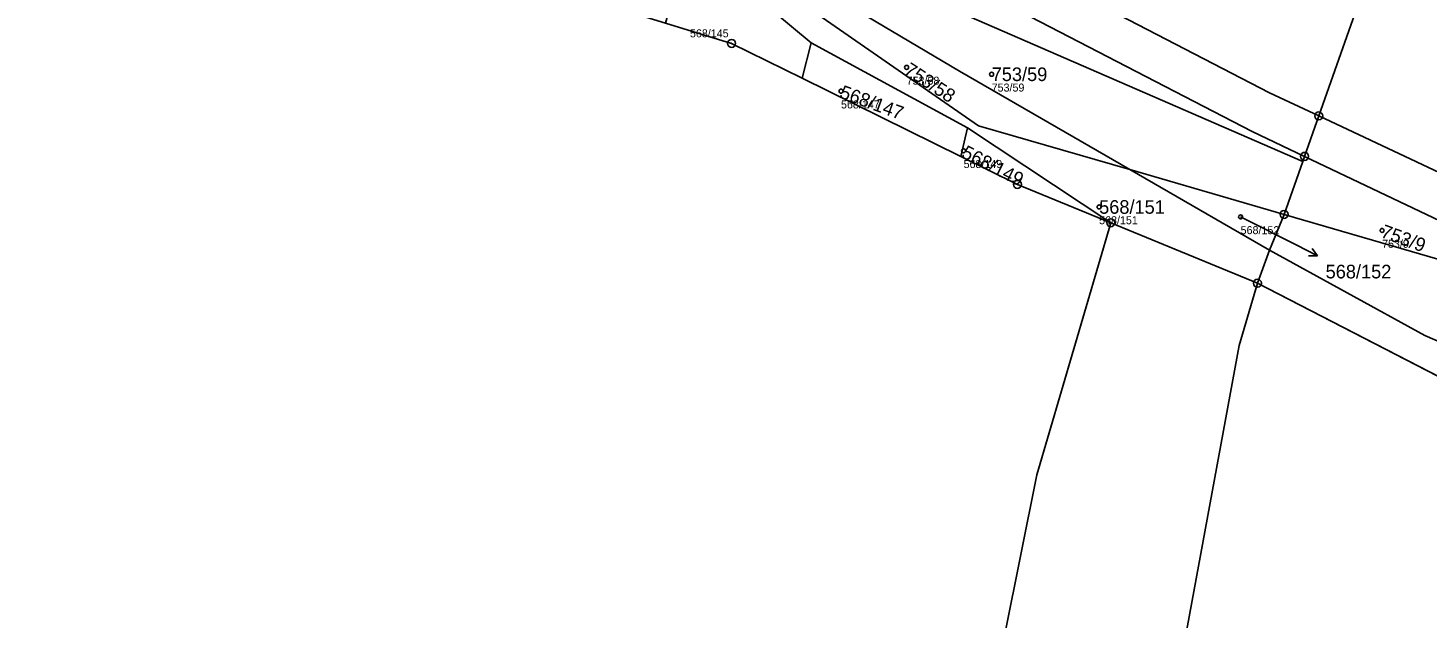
# Model space of a CAD drawing. Extents: x -732749 to -730903, y -1025757 to -1023435.
# Drawn here: x -731284.8 to -731109.9, y -1024442.6 to -1024368.8 of the extents above; entities that cross this region are included whole.
import ezdxf

# ---------------------------------------------------------------- set-up
doc = ezdxf.new("R2010")
doc.units = 0
for name, color, linetype in [('Definiční body', 7, 'Continuous'), ('Hranice parcel', 7, 'Continuous'), ('Parcelní čísla', 7, 'Continuous'), ('Polygon parcely', 7, 'Continuous'), ('Pop  PČ popisy', 7, 'Continuous'), ('Značky bodu BP', 7, 'Continuous')]:
    doc.layers.add(name, color=color, linetype=linetype)

msp = doc.modelspace()

# ---------------------------------------------------------------- linework, layer by layer
at = {"layer": 'Definiční body'}
for centre in [(-731174.97, -1024373.73), (-731164.34, -1024374.59), (-731183.17, -1024376.7), (-731167.85, -1024384.15), (-731150.91, -1024391.18), (-731133.22, -1024392.42), (-731115.54, -1024394.12)]:
    msp.add_circle(centre, 0.25, dxfattribs=at)
at = {"layer": 'Hranice parcel'}
for p, q in [((-731110.5, -1024343.03), (-731123.45, -1024379.8)), ((-731188.01, -1024375.09), (-731186.88, -1024370.67)), ((-731167.34, -1024381.29), (-731186.88, -1024370.67)), ((-731168.19, -1024384.86), (-731188.01, -1024375.09)), ((-731123.45, -1024379.8), (-731125.23, -1024384.85)), ((-731168.19, -1024384.86), (-731167.34, -1024381.29)), ((-731149.46, -1024393.15), (-731167.34, -1024381.29)), ((-731125.45, -1024385.48), (-731127.79, -1024392.11)), ((-731125.23, -1024384.85), (-731125.45, -1024385.48)), ((-731129.61, -1024396.6), (-731147.08, -1024386.51)), ((-731127.79, -1024392.11), (-731147.08, -1024386.51)), ((-731129.61, -1024396.6), (-731127.79, -1024392.11)), ((-731131.12, -1024400.71), (-731149.46, -1024393.15)), ((-731131.12, -1024400.71), (-731129.61, -1024396.6)), ((-731093.47, -1024420.12), (-731131.12, -1024400.71))]:
    msp.add_line(p, q, dxfattribs=at)
for points in [[(-731123.45, -1024379.8), (-731129.62, -1024376.9), (-731164.85, -1024358.61), (-731179.99, -1024347.06), (-731182.99, -1024344.27)], [(-731125.23, -1024384.85), (-731131.78, -1024381.73), (-731167.95, -1024362.97), (-731184.06, -1024350.96), (-731185.99, -1024349.07)], [(-731188.43, -1024352.97), (-731173.87, -1024364.4), (-731125.45, -1024385.48)], [(-731147.08, -1024386.51), (-731168.38, -1024374.2), (-731185.11, -1024364.22), (-731192.24, -1024359.06)], [(-731147.08, -1024386.51), (-731165.97, -1024381.02), (-731193.95, -1024361.63)], [(-731186.88, -1024370.67), (-731194.77, -1024364.06), (-731195.28, -1024363.64)], [(-731188.01, -1024375.09), (-731196.85, -1024370.73), (-731205.11, -1024368.19)], [(-731076.41, -1024398.3), (-731084.09, -1024396.18), (-731104.77, -1024388.59), (-731123.45, -1024379.8)], [(-731149.46, -1024393.15), (-731161.12, -1024388.35), (-731168.19, -1024384.86)], [(-731125.23, -1024384.85), (-731107.45, -1024393.31), (-731077.68, -1024402.89)], [(-731127.79, -1024392.11), (-731086.48, -1024404.11), (-731078.65, -1024406.4)], [(-731174.98, -1024506.17), (-731174.6, -1024503.96), (-731158.69, -1024424.65), (-731149.46, -1024393.15)], [(-731129.61, -1024396.6), (-731110.2, -1024407.27), (-731082.35, -1024419.33)], [(-731153.45, -1024517.26), (-731133.41, -1024408.52), (-731131.12, -1024400.71)]]:
    msp.add_lwpolyline(points, dxfattribs=at)
at = {"layer": 'Polygon parcely'}
for points in [[(-731174.6, -1024503.96), (-731158.69, -1024424.65), (-731149.46, -1024393.15), (-731161.12, -1024388.35), (-731168.19, -1024384.86), (-731188.01, -1024375.09), (-731196.85, -1024370.73), (-731205.11, -1024368.19), (-731225.02, -1024362.07), (-731236.29, -1024349.77), (-731241.55, -1024345.52), (-731258.62, -1024331.73), (-731268.94, -1024323.39), (-731273.03, -1024320.55), (-731287.55, -1024310.47), (-731298.38, -1024302.94), (-731300.13, -1024297.85), (-731302.67, -1024296.93), (-731317.3, -1024291.65), (-731324.84, -1024291.64), (-731342.73, -1024291.6), (-731349.47, -1024287.4), (-731384.29, -1024380.16)], [(-731092.92, -1024454.14), (-731090.85, -1024437.08), (-731092.69, -1024425.2), (-731093.47, -1024420.12), (-731131.12, -1024400.71), (-731133.41, -1024408.52), (-731153.45, -1024517.26)]]:
    msp.add_lwpolyline(points, dxfattribs=at)
for points in [[(-731110.5, -1024343.03), (-731163.99, -1024315.6), (-731166.08, -1024318.81), (-731168.81, -1024323.3), (-731182.99, -1024344.27), (-731179.99, -1024347.06), (-731164.85, -1024358.61), (-731129.62, -1024376.9), (-731123.45, -1024379.8)], [(-731066.27, -1024361.65), (-731110.5, -1024343.03), (-731123.45, -1024379.8), (-731104.77, -1024388.59), (-731084.09, -1024396.18), (-731076.41, -1024398.3)], [(-731164.85, -1024358.61), (-731179.99, -1024347.06), (-731182.99, -1024344.27), (-731185.99, -1024349.07), (-731184.06, -1024350.96), (-731167.95, -1024362.97), (-731131.78, -1024381.73), (-731125.23, -1024384.85), (-731123.45, -1024379.8), (-731129.62, -1024376.9)], [(-731167.95, -1024362.97), (-731184.06, -1024350.96), (-731185.99, -1024349.07), (-731188.43, -1024352.97), (-731173.87, -1024364.4), (-731125.45, -1024385.48), (-731125.23, -1024384.85), (-731131.78, -1024381.73)], [(-731127.79, -1024392.11), (-731125.45, -1024385.48), (-731173.87, -1024364.4), (-731188.43, -1024352.97), (-731192.24, -1024359.06), (-731185.11, -1024364.22), (-731168.38, -1024374.2), (-731147.08, -1024386.51)], [(-731186.88, -1024370.67), (-731194.77, -1024364.06), (-731195.28, -1024363.64), (-731202.25, -1024357.88), (-731205.11, -1024368.19), (-731196.85, -1024370.73), (-731188.01, -1024375.09)], [(-731192.24, -1024359.06), (-731193.95, -1024361.63), (-731165.97, -1024381.02), (-731147.08, -1024386.51), (-731168.38, -1024374.2), (-731185.11, -1024364.22)], [(-731147.08, -1024386.51), (-731165.97, -1024381.02), (-731193.95, -1024361.63), (-731195.28, -1024363.64), (-731194.77, -1024364.06), (-731186.88, -1024370.67), (-731167.34, -1024381.29), (-731149.46, -1024393.15), (-731131.12, -1024400.71), (-731129.61, -1024396.6)], [(-731168.19, -1024384.86), (-731167.34, -1024381.29), (-731186.88, -1024370.67), (-731188.01, -1024375.09)], [(-731107.45, -1024393.31), (-731077.68, -1024402.89), (-731076.41, -1024398.3), (-731084.09, -1024396.18), (-731104.77, -1024388.59), (-731123.45, -1024379.8), (-731125.23, -1024384.85)], [(-731149.46, -1024393.15), (-731167.34, -1024381.29), (-731168.19, -1024384.86), (-731161.12, -1024388.35)], [(-731127.79, -1024392.11), (-731086.48, -1024404.11), (-731078.65, -1024406.4), (-731077.68, -1024402.89), (-731107.45, -1024393.31), (-731125.23, -1024384.85), (-731125.45, -1024385.48)], [(-731129.61, -1024396.6), (-731127.79, -1024392.11), (-731147.08, -1024386.51)], [(-731082.35, -1024419.33), (-731078.65, -1024406.4), (-731086.48, -1024404.11), (-731127.79, -1024392.11), (-731129.61, -1024396.6), (-731110.2, -1024407.27)], [(-731174.98, -1024506.17), (-731153.45, -1024517.26), (-731133.41, -1024408.52), (-731131.12, -1024400.71), (-731149.46, -1024393.15), (-731158.69, -1024424.65), (-731174.6, -1024503.96)], [(-731091.65, -1024425.59), (-731084.67, -1024427.49), (-731082.35, -1024419.33), (-731110.2, -1024407.27), (-731129.61, -1024396.6), (-731131.12, -1024400.71), (-731093.47, -1024420.12), (-731092.69, -1024425.2)]]:
    msp.add_lwpolyline(points, close=True, dxfattribs=at)
at = {"layer": 'Pop  PČ popisy'}
for p, q in [((-731133.22, -1024392.42), (-731126.28, -1024395.93)), ((-731126.28, -1024395.93), (-731123.61, -1024397.29)), ((-731123.61, -1024397.29), (-731124.73, -1024397.28)), ((-731123.61, -1024397.29), (-731124.27, -1024396.39))]:
    msp.add_line(p, q, dxfattribs=at)
at = {"layer": 'Značky bodu BP'}
for centre, radius in [((-731196.85, -1024370.73), 0.5), ((-731196.85, -1024370.73), 0.0303), ((-731123.45, -1024379.8), 0.5), ((-731123.45, -1024379.8), 0.0303), ((-731125.23, -1024384.85), 0.5), ((-731125.23, -1024384.85), 0.0303), ((-731161.12, -1024388.35), 0.5), ((-731161.12, -1024388.35), 0.0303), ((-731149.46, -1024393.15), 0.5), ((-731127.79, -1024392.11), 0.5), ((-731127.79, -1024392.11), 0.0303), ((-731149.46, -1024393.15), 0.0303), ((-731131.12, -1024400.71), 0.5), ((-731131.12, -1024400.71), 0.0303)]:
    msp.add_circle(centre, radius, dxfattribs=at)

# ---------------------------------------------------------------- texts
at = {"layer": 'Definiční body'}
for s, p in [('568/145', (-731202.05, -1024369.97)), ('753/58', (-731174.97, -1024375.89)), ('753/59', (-731164.34, -1024376.75)), ('568/147', (-731183.17, -1024378.86)), ('568/149', (-731167.85, -1024386.31)), ('568/151', (-731150.91, -1024393.34)), ('568/152', (-731133.22, -1024394.58)), ('753/9', (-731115.54, -1024396.28))]:
    msp.add_text(s, height=1, dxfattribs=at).set_placement(p)
at = {"layer": 'Parcelní čísla'}
for s, rotation, p in [('753/58', 327, (-731175.43, -1024374.44)), ('568/147', 340, (-731183.46, -1024377.5)), ('568/149', 333, (-731168.23, -1024384.91)), ('753/9', 340, (-731115.83, -1024394.92))]:
    msp.add_text(s, height=1.7, rotation=rotation, dxfattribs=at).set_placement(p)
for s, p in [('753/59', (-731164.34, -1024375.44)), ('568/151', (-731150.91, -1024392.03)), ('568/152', (-731122.6, -1024400.11))]:
    msp.add_text(s, height=1.7, dxfattribs=at).set_placement(p)

doc.saveas('drawing.dxf')
